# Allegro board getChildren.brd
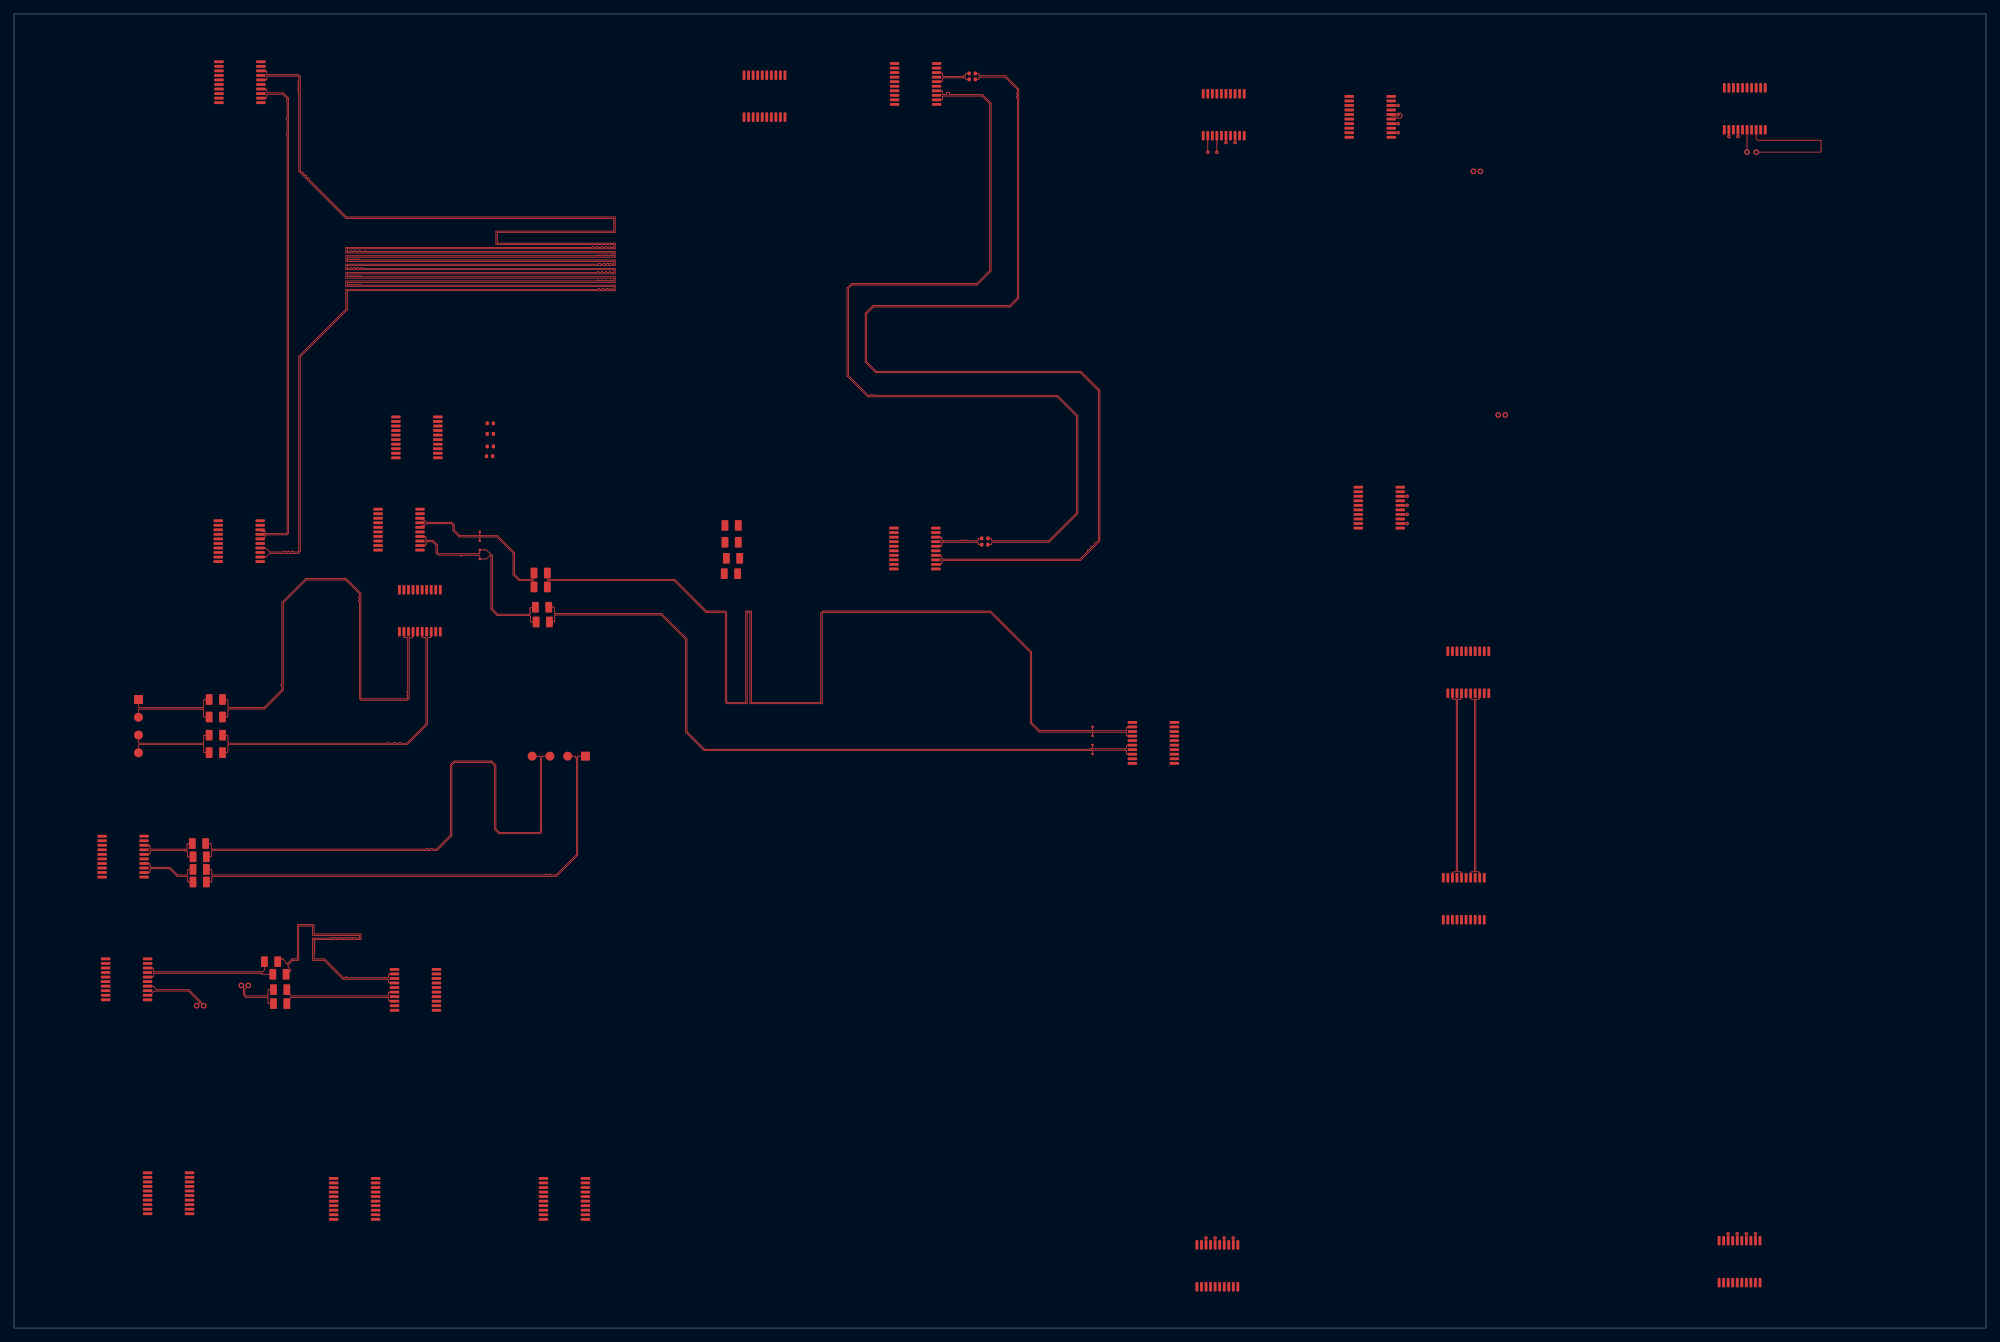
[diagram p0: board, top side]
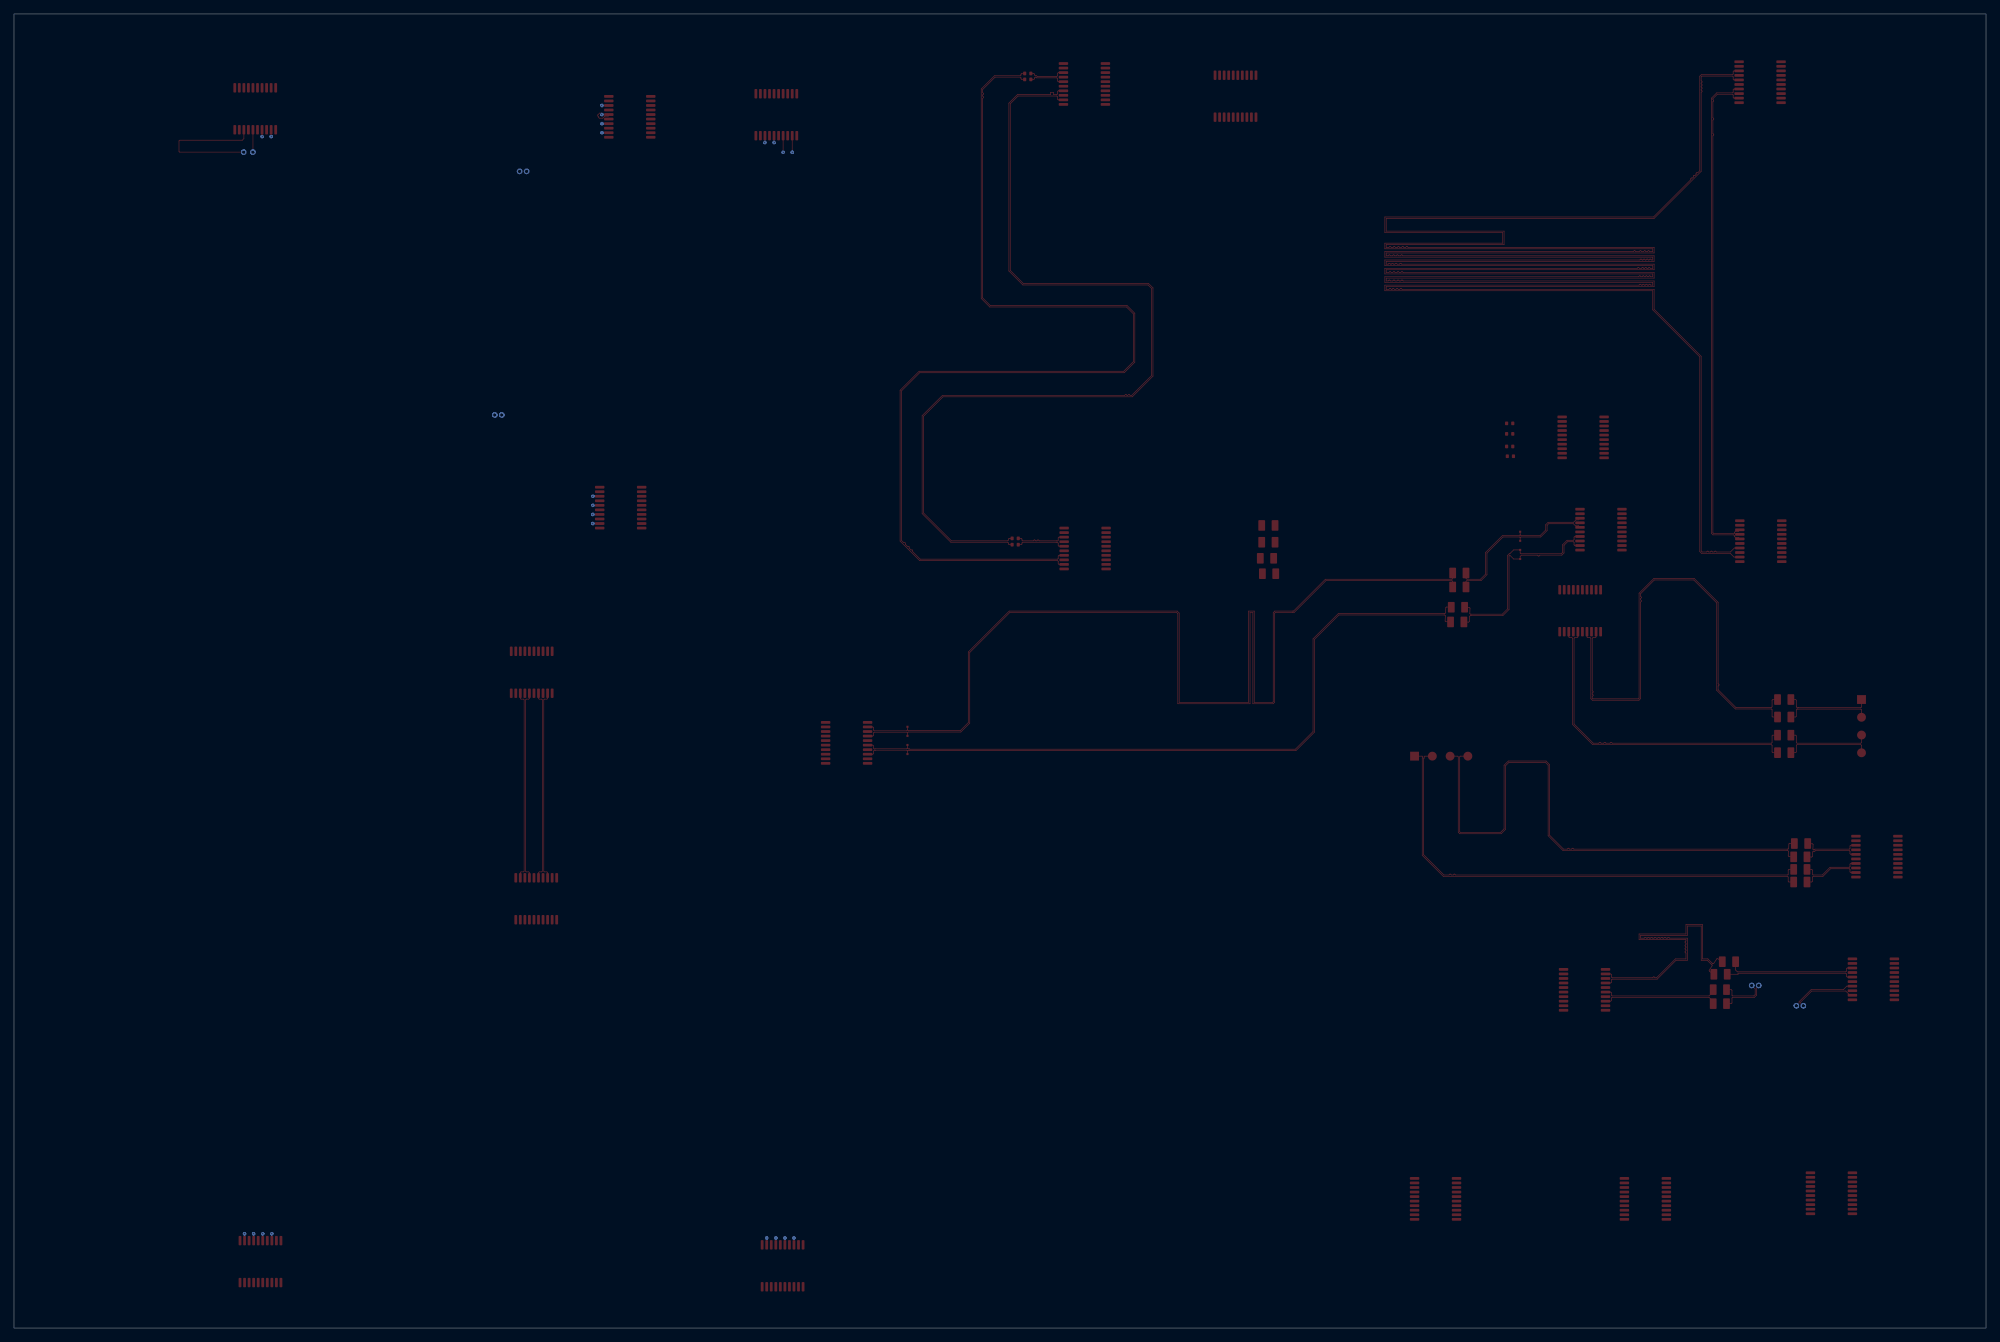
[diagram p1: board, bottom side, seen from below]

Outline 281.94 x 187.96 mm; copper layers: TOP, LAYER2, LAYER3, LAYER4, LAYER5, LAYER6, LAYER7, LAYER8, LAYER9, LAYER10, LAYER11, LAYER12, LAYER13, LAYER14, LAYER15, LAYER16, LAYER17, BOTTOM. Coordinates in mm from the lower left corner of the outline.
Outline path: 0,187.96 281.94,187.96 281.94,0 0,0 0,187.96

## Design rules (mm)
constraint set DEFAULT: min track width 0.1, pair gap 0.15
net group CLS1: nets NET_A_N NET_AAA_P
net group CONN_MIRROR_NET_G_N: nets CONN_MIRROR_NET_G_N UNNAMED_1_74244_I71_A_3
net group CONN_MIRROR_NET_G_P: nets CONN_MIRROR_NET_G_P UNNAMED_1_74244_I71_A_1
net group CONN_MIRROR_NET_H_N: nets CONN_MIRROR_NET_H_N UNNAMED_1_74244_I71_A_2
net group CONN_MIRROR_NET_H_P: nets CONN_MIRROR_NET_H_P UNNAMED_1_74244_I71_A
net group CONN_NET_G_N: nets CONN_NET_G_N UNNAMED_1_74244_I50_A_1
net group CONN_NET_G_P: nets CONN_NET_G_P UNNAMED_1_74244_I50_A
net group CONN_NET_H_N: nets CONN_NET_H_N UNNAMED_1_74244_I50_A_3
net group CONN_NET_H_P: nets CONN_NET_H_P UNNAMED_1_74244_I50_A_2
net group DP2: nets NET_AAA_N NET_BBB_N
net group NET_C_N: nets NET_C_N UNNAMED_1_74244_I6_A_2
net group NET_C_P: nets NET_C_P UNNAMED_1_74244_I6_A_3
net group NET_D_N: nets NET_D_N UNNAMED_1_74244_I6_A
net group NET_D_P: nets NET_D_P UNNAMED_1_74244_I6_A_1
net group NET_G_N: nets NET_G_N UNNAMED_1_74244_I12_A_2
net group NET_G_P: nets NET_G_P UNNAMED_1_74244_I12_A_3
net group NET_H_N: nets NET_H_N UNNAMED_1_74244_I12_A
net group NET_H_P: nets NET_H_P UNNAMED_1_74244_I12_A_1
net group TP_G_N: nets TP_G_N UNNAMED_1_74244_I44_A_2
net group TP_G_P: nets TP_G_P UNNAMED_1_74244_I44_A_3
net group TP_H_N: nets TP_H_N UNNAMED_1_74244_I44_A
net group TP_H_P: nets TP_H_P UNNAMED_1_74244_I44_A_1
net group DP1: nets NET_A_P
net group RC_NET_G_N: nets RC_NET_G_N UNNAMED_1_74244_I38_A_1 UNNAMED_1_74244_I39_Y
net group RC_NET_G_P: nets RC_NET_G_P UNNAMED_1_74244_I38_A UNNAMED_1_CAPUNPOL5_I34_A
net group RC_NET_H_N: nets RC_NET_H_N UNNAMED_1_74244_I38_A_3 UNNAMED_1_CAPUNPOL5_I36_A
net group RC_NET_H_P: nets RC_NET_H_P UNNAMED_1_74244_I38_A_2 UNNAMED_1_CAPUNPOL5_I35_A

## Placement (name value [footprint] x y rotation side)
C1  10p  [511-BYZ10902-70]  38.05 48.4 0 top
C2  10p  [511-BYZ10902-70]  36.75 52.4 0 top
C3  10p  [511-BYZ10902-70]  38.05 46.4 0 top
C4  10p  [511-BYZ10902-70]  37.95 50.6 0 top
C5  10p  [511-BYZ10902-70]  102.8 110.1 0 top
C6  10p  [511-BYZ10902-70]  75.5 103.1 0 top
C7  10p  [511-BYZ10902-70]  102.6 114.8 0 top
C8  10p  [511-BYZ10902-70]  75.3 108 0 top
C9  10p  [511-BYZ10902-70]  102.5 107.9 0 top
C10  10p  [511-BYZ10902-70]  75.6 101 0 top
C11  10p  [511-BYZ10902-70]  102.6 112.4 0 top
C12  10p  [511-BYZ10902-70]  75.3 106 0 top
C13  10p  [511-BYZ10902-70]  28.85 84.8 0 top
C14  10p  [511-BYZ10902-70]  28.85 89.9 0 top
C15  10p  [511-BYZ10902-70]  28.85 82.3 0 top
C16  10p  [511-BYZ10902-70]  28.85 87.4 0 top
C17  10p  [511-BYZ10902-70]  26.55 67.4 180 top
C18  10p  [511-BYZ10902-70]  26.55 63.8 180 top
C19  10p  [511-BYZ10902-70]  26.45 69.3 180 top
C20  10p  [511-BYZ10902-70]  26.55 65.6 180 top
D1  -  [511-BYZ20916-63_TOP]  32.3 178.2 270 top
D2  -  [511-BYZ20916-63_TOP]  128.9 177.95 270 top
D3  -  [511-BYZ20916-63_TOP]  22.1 19.27 270 top
D4  -  [511-BYZ20916-63_TOP]  16.1 49.88 270 top
D5  -  [511-BYZ20916-63_TOP]  32.2 112.55 90 top
D6  -  [511-BYZ20916-63_TOP]  128.8 111.5 90 top
D7  -  [511-BYZ20916-63_TOP]  57.4 48.38 270 top
D8  -  [511-BYZ20916-63_TOP]  78.7 18.48 270 top
D9  -  [511-BYZ20916-63_TOP]  48.7 18.48 270 top
D10  -  [511-BYZ20916-63_TOP]  193.9 173.25 270 top
D11  -  [511-BYZ20916-63_TOP]  247.45 174.4 0 top
D12  -  [511-BYZ20916-63_TOP]  195.2 117.35 90 top
D13  -  [511-BYZ20916-63_TOP]  246.7 9.5 0 top
D14  -  [511-BYZ20916-63_TOP]  172.95 173.55 0 top
D15  -  [511-BYZ20916-63_TOP]  172.05 8.9 0 top
D16  -  [511-BYZ20916-63_TOP]  57.6 127.4 270 top
D17  -  [511-BYZ20916-63_TOP]  55.05 114.2 270 top
D18  -  [511-BYZ20916-63_TOP]  107.3 176.2 0 top
D19  -  [511-BYZ20916-63_TOP]  162.9 83.7 270 top
D20  -  [511-BYZ20916-63_TOP]  58.02 102.6 0 top
D21  -  [511-BYZ20916-63_TOP]  207.28 61.4 0 top
D22  -  [511-BYZ20916-63_TOP]  207.93 93.8 0 top
D23  -  [511-BYZ20916-63_TOP]  15.6 67.42 90 top
R1  3.3k  [501-BYZ20902-48_TOP]  138.8 112.95 180 top
R2  3.3k  [501-BYZ20902-48_TOP]  137 179.45 0 top
R3  3.3k  [501-BYZ20902-48_TOP]  137 178.6 0 top
R4  3.3k  [501-BYZ20902-48_TOP]  138.8 112.05 180 top
R5  3.3k  [501-BYZ20902-48_TOP]  68.1 129.4 0 top
R6  3.3k  [501-BYZ20902-48_TOP]  68.1 127.9 0 top
R7  3.3k  [501-BYZ20902-48_TOP]  68.1 126.1 0 top
R8  3.3k  [501-BYZ20902-48_TOP]  68 124.7 0 top
TP1  -  [505-BYZ11988-1]  66.6 113.9 0 top
TP2  -  [505-BYZ11988-1]  66.6 112.6 0 top
TP3  -  [505-BYZ11988-1]  66.6 111.3 0 top
TP4  -  [505-BYZ11988-1]  66.6 110 0 top
TP5  -  [505-BYZ11988-1]  154.2 86 0 top
TP6  -  [505-BYZ11988-1]  154.2 82.1 0 top
TP7  -  [505-BYZ11988-1]  154.2 84.7 0 top
TP8  -  [505-BYZ11988-1]  154.2 83.4 0 top
X1  -  [501-BYZ10901-287]  17.8 89.9 0 top
X2  -  [501-BYZ10901-287]  81.7 81.8 270 top

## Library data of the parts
C1-C20 = RJC543458: alternate symbols: (T:511-BYZ10902-70,511-BYZ20902-70_TOP;B:511-BYZ10902-70,511-BYZ20902-70_BOT); part number: RJC543458-10P; signal model: DEFAULT_CAPACITOR_10.000000pF_2_1
D1-D23 = 74VHC244: alternate symbols: (T:511-BYZ20916-63_TOP;B:511-BYZ20916-63_BOT); part number: 74VHC244-RYT3356008/2C,74VHC244MTC
R1-R8 = REP62265: alternate symbols: (T:501-BYZ20902-48_TOP,501-BYZ10902-503;B:501-BYZ20902-48_BOT,501-BYZ10902-503); part number: REP62265-3.3K; signal model: DEFAULT_RESISTOR_3300OHM_2_1
TP1-TP8 = TP_RND_NH_48: alternate symbols: (505-BYZ11988-1); part number: TP_RND_NH_48-TP_RND_NH_48
X1 X2 = RPV403164/802: alternate symbols: (501-BYZ10901-287); part number: RPV403164/802-RPV403164/802

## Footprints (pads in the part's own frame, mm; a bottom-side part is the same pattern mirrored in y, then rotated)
501-BYZ10901-287
  rect 1.27x1.27 smd: 1(0,0)
  round 1.27 smd: 2(0,-2.54) J1(0,-5.08) J2(0,-7.62)
501-BYZ20902-48_TOP
  custom 0.114x0.114 smd: 1(-0.44,0) 2(0.44,0)
505-BYZ11988-1
  rect 0.3x0.3 smd: 1(0,0)
511-BYZ10902-70
  custom 0.242x0.242 smd: 1(-0.953,0) 2(0.953,0)
511-BYZ20916-63_TOP
  custom 0.1x0.1 smd: 1(-2.925,-3) 2(-2.275,-3) 3(-1.625,-3) 4(-0.975,-3) 5(-0.325,-3) 6(0.325,-3) 7(0.975,-3) 8(1.625,-3) 9(2.275,-3) 10(2.925,-3) 11(2.925,3) 12(2.275,3) 13(1.625,3) 14(0.975,3) 15(0.325,3) 16(-0.325,3) 17(-0.975,3) 18(-1.625,3) 19(-2.275,3) 20(-2.925,3)

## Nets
PGND: D3.10 D4.10 D5.10 D6.10 D7.10 D8.10 D9.10
CONN_MIRROR_NET_G_N: C20.1 X2.2(P<1>)
CONN_MIRROR_NET_G_P: C18.1 X2.1
CONN_MIRROR_NET_H_N: C19.1 X2.J2
CONN_MIRROR_NET_H_P: C17.1 X2.J1
CONN_NET_G_N: C16.1 X1.2(P<1>)
CONN_NET_G_P: C14.1 X1.1
CONN_NET_H_N: C15.1 X1.J2
CONN_NET_H_P: C13.1 X1.J1
NET_A_N: D1.16 D5.4
NET_A_P: D1.18 D5.2
NET_AAA_N: D10.16 D12.4
NET_AAA_P: D10.18 D12.2
NET_B_N: D1.12 D5.8
NET_B_P: D1.14 D5.6
NET_BBB_N: D10.12 D12.8
NET_BBB_P: D10.14 D12.6
NET_C_N: D2.16 R3.1
NET_C_P: D2.18 R2.1
NET_CCC_N: D11.4 D13.16
NET_CCC_P: D11.2 D13.18
NET_D_N: D2.12 R1.1
NET_D_P: D2.14 R4.1
NET_DDD_N: D11.8 D13.12
NET_DDD_P: D11.6 D13.14
NET_E_N: D3.16 D8.4 D9.4
NET_E_P: D3.18 D8.2 D9.2
NET_EEE_N: D14.4 D15.16
NET_EEE_P: D14.2 D15.18
NET_F_N: D3.12 D8.8 D9.8
NET_F_P: D3.14 D8.6 D9.6
NET_FFF_N: D14.8 D15.12
NET_FFF_P: D14.6 D15.14
NET_G_N: C4.1 D4.16
NET_G_P: C2.1 D4.18
NET_H_N: C3.1 D4.12
NET_H_P: C1.1 D4.14
P2_3V: D3.20(U+) D4.20(U+) D5.20(U+) D6.20(U+) D7.20(U+) D8.20(U+) D9.20(U+)
RC_NET_G_N: C11.1 R6.2(Y)
RC_NET_G_P: D16.18 R5.1
RC_NET_H_N: D16.12 R8.1
RC_NET_H_P: D16.14 R7.1
TP_G_N: C12.1 D17.16 TP2.1(P)
TP_G_P: C8.1 D17.18 TP1.1(P)
TP_H_N: C10.1 D17.12 TP4.1(P)
TP_H_P: C6.1 D17.14 TP3.1(P)
UNCOUPLED_NET_EEE_N: D21.16 D22.4
UNCOUPLED_NET_EEE_P: D21.18 D22.2
UNCOUPLED_NET_FFF_N: D21.12 D22.8
UNCOUPLED_NET_FFF_P: D21.14 D22.6
UNNAMED_1_74244_I6_A: D6.8 R1.2(Y)
UNNAMED_1_74244_I6_A_1: D6.6 R4.2(Y)
UNNAMED_1_74244_I6_A_2: D6.4 R3.2(Y)
UNNAMED_1_74244_I6_A_3: D6.2 R2.2(Y)
UNNAMED_1_74244_I12_A: C3.2(Y) D7.8
UNNAMED_1_74244_I12_A_1: C1.2(Y) D7.6
UNNAMED_1_74244_I12_A_2: C4.2(Y) D7.4
UNNAMED_1_74244_I12_A_3: C2.2(Y) D7.2
UNNAMED_1_74244_I38_A: C7.2(Y) D18.2
UNNAMED_1_74244_I38_A_1: C11.2(Y) D18.4
UNNAMED_1_74244_I38_A_2: C5.2(Y) D18.6
UNNAMED_1_74244_I38_A_3: C9.2(Y) D18.8
UNNAMED_1_74244_I39_Y: D16.16 R6.1
UNNAMED_1_74244_I44_A: C10.2(Y) D19.8 TP6.1(P)
UNNAMED_1_74244_I44_A_1: C6.2(Y) D19.6 TP8.1(P)
UNNAMED_1_74244_I44_A_2: C12.2(Y) D19.4 TP7.1(P)
UNNAMED_1_74244_I44_A_3: C8.2(Y) D19.2 TP5.1(P)
UNNAMED_1_74244_I50_A: C14.2(Y) D20.2
UNNAMED_1_74244_I50_A_1: C16.2(Y) D20.4
UNNAMED_1_74244_I50_A_2: C13.2(Y) D20.6
UNNAMED_1_74244_I50_A_3: C15.2(Y) D20.8
UNNAMED_1_74244_I71_A: C17.2(Y) D23.6
UNNAMED_1_74244_I71_A_1: C18.2(Y) D23.2
UNNAMED_1_74244_I71_A_2: C19.2(Y) D23.8
UNNAMED_1_74244_I71_A_3: C20.2(Y) D23.4
UNNAMED_1_CAPUNPOL5_I34_A: C7.1 R5.2(Y)
UNNAMED_1_CAPUNPOL5_I35_A: C5.1 R7.2(Y)
UNNAMED_1_CAPUNPOL5_I36_A: C9.1 R8.2(Y)

Pads without a net: D1 1 2 3 4 5 6 7 8 9 10 11 13 15 17 19 20; D2 1 2 3 4 5 6 7 8 9 10 11 13 15 17 19 20; D3 1 2 3 4 5 6 7 8 9 11 13 15 17 19; D4 1 2 3 4 5 6 7 8 9 11 13 15 17 19; D5 1 3 5 7 9 11 12 13 14 15 16 17 18 19; D6 1 3 5 7 9 11 12 13 14 15 16 17 18 19; D7 1 3 5 7 9 11 12 13 14 15 16 17 18 19; D8 1 3 5 7 9 11 12 13 14 15 16 17 18 19; D9 1 3 5 7 9 11 12 13 14 15 16 17 18 19; D10 1 2 3 4 5 6 7 8 9 10 11 13 15 17 19 20; D11 1 3 5 7 9 10 11 12 13 14 15 16 17 18 19 20; D12 1 3 5 7 9 10 11 12 13 14 15 16 17 18 19 20; D13 1 2 3 4 5 6 7 8 9 10 11 13 15 17 19 20; D14 1 3 5 7 9 10 11 12 13 14 15 16 17 18 19 20; D15 1 2 3 4 5 6 7 8 9 10 11 13 15 17 19 20; D16 1 2 3 4 5 6 7 8 9 10 11 13 15 17 19 20; D17 1 2 3 4 5 6 7 8 9 10 11 13 15 17 19 20; D18 1 3 5 7 9 10 11 12 13 14 15 16 17 18 19 20; D19 1 3 5 7 9 10 11 12 13 14 15 16 17 18 19 20; D20 1 3 5 7 9 10 11 12 13 14 15 16 17 18 19 20; D21 1 2 3 4 5 6 7 8 9 10 11 13 15 17 19 20; D22 1 3 5 7 9 10 11 12 13 14 15 16 17 18 19 20; D23 1 3 5 7 9 10 11 12 13 14 15 16 17 18 19 20

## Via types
v1: diameter 0.5, hole 0.2, TOP to BOTTOM, 22 vias
v2: diameter 0.8, hole 0.5, TOP to BOTTOM, 10 vias

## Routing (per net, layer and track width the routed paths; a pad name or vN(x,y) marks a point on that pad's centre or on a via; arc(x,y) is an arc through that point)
CONN_MIRROR_NET_G_N: length 70.2
  TOP w0.1: C20.1 28.18,65.6 28.28,65.5 28.28,64.9 28.38,64.8 75.83,64.8 75.95,64.92 76.05,64.92 76.17,64.8 76.43,64.8 76.55,64.92 76.65,64.92 76.77,64.8 77.5,64.8 80.4,67.7 80.4,81.45 80.33,81.52 80.33,81.7 80.23,81.8 X2.2
CONN_MIRROR_NET_G_P: length 70.4
  TOP w0.1: C18.1 28.18,63.8 28.28,63.9 28.28,64.5 28.38,64.6 77.58,64.6 80.6,67.62 80.6,81.53 80.53,81.6 80.53,81.7 80.63,81.8 X2.1
CONN_MIRROR_NET_H_N: length 81.4
  TOP w0.1: C19.1 28.08,69.34 28.19,69.24 28.22,68.59 28.33,68.5 28.42,68.5 58.93,68.5 59.05,68.62 59.15,68.62 59.27,68.5 59.53,68.5 59.65,68.62 59.75,68.62 59.87,68.5 60.4,68.5 62.4,70.5 62.4,80.6 62.9,81.1 68.3,81.1 68.9,80.5 68.9,71.4 69.4,70.9 75.15,70.9 75.25,71 75.25,81.7 75.15,81.8 X2.J2
CONN_MIRROR_NET_H_P: length 81.5
  TOP w0.1: C17.1 28.18,67.44 28.28,67.54 28.24,68.19 28.34,68.3 28.43,68.3 60.48,68.3 62.6,70.42 62.6,80.52 62.98,80.9 68.22,80.9 68.7,80.42 68.7,71.32 69.32,70.7 75.23,70.7 75.45,70.92 75.45,81.7 75.55,81.8 X2.J1
CONN_NET_G_N: length 12.3
  TOP w0.1: C16.1 27.22,87.4 27.12,87.5 27.12,88.45 27.02,88.55 26.92,88.55 26.9,88.53 17.9,88.53 17.8,88.43 X1.2
CONN_NET_G_P: length 12.3
  TOP w0.1: X1.1 17.8,88.83 17.9,88.73 26.82,88.73 26.84,88.75 27.02,88.75 27.12,88.85 27.12,89.8 27.22,89.9 C14.1
CONN_NET_H_N: length 12.2
  TOP w0.1: C15.1 27.22,82.3 27.12,82.4 27.12,83.35 27.02,83.45 17.9,83.45 17.8,83.35 X1.J2
CONN_NET_H_P: length 12.2
  TOP w0.1: X1.J1 17.8,83.75 17.9,83.65 27.02,83.65 27.12,83.75 27.12,84.7 27.22,84.8 C13.1
NET_A_N: length 581.6
  TOP w0.1: D5.4 35.98,111.58 36.55,111 38.53,111 38.65,111.12 38.75,111.12 38.87,111 39.08,111 39.2,111.12 39.3,111.12 39.42,111 39.63,111 39.75,111.12 39.85,111.12 39.97,111 40.58,111 40.73,111.15 40.73,139 47.45,145.72 47.45,148.58 83.48,148.58 83.6,148.7 83.7,148.7 83.82,148.58 84.03,148.58 84.15,148.7 84.25,148.7 84.37,148.58 84.58,148.58 84.7,148.7 84.8,148.7 84.92,148.58 85.03,148.58 85.15,148.7 85.25,148.7 85.37,148.58 85.75,148.58 85.75,148.98 47.45,148.98 47.45,149.78 83.33,149.78 83.45,149.9 83.55,149.9 83.67,149.78 83.88,149.78 84,149.9 84.1,149.9 84.22,149.78 84.48,149.78 84.6,149.9 84.7,149.9 84.82,149.78 85.13,149.78 85.25,149.9 85.35,149.9 85.47,149.78 85.75,149.78 85.75,150.18 47.45,150.18 47.45,150.98 83.33,150.98 83.45,151.1 83.55,151.1 83.67,150.98 83.88,150.98 84,151.1 84.1,151.1 84.22,150.98 84.48,150.98 84.6,151.1 84.7,151.1 84.82,150.98 85.03,150.98 85.15,151.1 85.25,151.1 85.37,150.98 85.75,150.98 85.75,151.38 47.45,151.38 47.45,152.18 83.53,152.18 83.65,152.3 83.75,152.3 83.87,152.18 84.18,152.18 84.3,152.3 84.4,152.3 84.52,152.18 84.69,152.18 84.81,152.3 84.91,152.3 85.03,152.18 85.13,152.18 85.25,152.3 85.35,152.3 85.47,152.18 85.75,152.18 85.75,152.58 47.45,152.58 47.45,153.38 83.38,153.38 83.5,153.5 83.6,153.5 83.72,153.38 83.98,153.38 84.1,153.5 84.2,153.5 84.32,153.38 84.53,153.38 84.65,153.5 84.75,153.5 84.87,153.38 85.13,153.38 85.25,153.5 85.35,153.5 85.47,153.38 85.75,153.38 85.75,153.78 47.45,153.78 47.45,154.58 82.63,154.58 82.75,154.7 82.85,154.7 82.97,154.58 83.23,154.58 83.35,154.7 83.45,154.7 83.57,154.58 83.83,154.58 83.95,154.7 84.05,154.7 84.17,154.58 84.43,154.58 84.55,154.7 84.65,154.7 84.77,154.58 85.03,154.58 85.15,154.7 85.25,154.7 85.37,154.58 85.75,154.58 85.75,154.98 68.9,154.98 68.9,156.9 85.75,156.9 85.75,158.72 47.45,158.72 40.73,165.45 40.73,176.73 40.6,176.85 40.6,176.95 40.73,177.07 40.73,177.18 40.6,177.3 40.6,177.4 40.73,177.52 40.73,177.63 40.6,177.75 40.6,177.85 40.73,177.97 40.73,178.08 40.6,178.2 40.6,178.3 40.73,178.42 40.73,178.97 40.62,179.07 36.25,179.07 36.15,178.97 36.15,178.62 36.05,178.53 D1.16
NET_A_P: length 581.4
  TOP w0.1: 35.2,110.28 36.02,110.28 36.55,110.8 40.66,110.8 40.92,111.07 40.92,138.92 47.65,145.64 47.65,148.38 85.95,148.38 85.95,149.18 49.6,149.18 49.48,149.3 49.38,149.3 49.26,149.18 49.16,149.18 49.04,149.3 48.94,149.3 48.82,149.18 48.72,149.18 48.6,149.3 48.5,149.3 48.38,149.18 48.27,149.18 48.15,149.3 48.05,149.3 47.93,149.18 47.65,149.18 47.65,149.58 85.95,149.58 85.95,150.38 49.67,150.38 49.55,150.5 49.45,150.5 49.33,150.38 49.16,150.38 49.04,150.5 48.94,150.5 48.82,150.38 48.72,150.38 48.6,150.5 48.5,150.5 48.38,150.38 48.27,150.38 48.15,150.5 48.05,150.5 47.93,150.38 47.65,150.38 47.65,150.78 85.95,150.78 85.95,151.58 49.87,151.58 49.75,151.7 49.65,151.7 49.53,151.58 49.27,151.58 49.15,151.7 49.05,151.7 48.93,151.58 48.82,151.58 48.7,151.7 48.6,151.7 48.48,151.58 48.32,151.58 48.2,151.7 48.1,151.7 47.98,151.58 47.65,151.58 47.65,151.98 85.95,151.98 85.95,152.78 49.5,152.78 49.38,152.9 49.28,152.9 49.16,152.78 49.05,152.78 48.93,152.9 48.83,152.9 48.71,152.78 48.61,152.78 48.49,152.9 48.39,152.9 48.27,152.78 48.17,152.78 48.05,152.9 47.95,152.9 47.83,152.78 47.65,152.78 47.65,153.18 85.95,153.18 85.95,153.98 50.42,153.98 50.3,154.1 50.2,154.1 50.08,153.98 49.57,153.98 49.45,154.1 49.35,154.1 49.23,153.98 48.97,153.98 48.85,154.1 48.75,154.1 48.63,153.98 48.42,153.98 48.3,154.1 48.2,154.1 48.08,153.98 47.65,153.98 47.65,154.38 85.95,154.38 85.95,155.18 69.1,155.18 69.1,156.7 85.95,156.7 85.95,158.93 47.53,158.93 42.2,164.26 42.2,164.43 42.13,164.5 41.96,164.5 41.82,164.63 41.82,164.8 41.75,164.87 41.58,164.87 41.45,165.01 41.45,165.18 41.38,165.25 41.21,165.25 40.92,165.53 40.92,179.06 40.71,179.28 36.25,179.28 36.15,179.38 36.15,179.72 36.05,179.82 D1.18
NET_AAA_N: length 107
  TOP w0.1: D12.4 v1(199.18,116.38) ; D10.16 196.9,173.45 197,173.35 197.46,173.35 197.76,173.05 198.25,173.05 198.35,173.15 198.35,173.25 198.48,173.38 198.48,173.52 198.22,173.78 198.08,173.78 v1(197.88,173.57)
  LAYER5 w0.1: v2(212.2,130.6) 212.6,130.2 212.6,118.48 209.94,115.83 199.28,115.83 199.18,115.92 v1(199.18,116.38) ; v1(197.88,173.57) 197.88,174.03 197.97,174.12 205.09,174.12 209.05,170.17 209.05,165.85 v2(208.65,165.45)
  LAYER6 w0.1: v2(212.2,130.6) 212.6,131 212.6,146.54 212.48,146.66 212.48,146.76 212.6,146.88 212.6,146.98 212.48,147.1 212.48,147.2 212.6,147.32 212.6,147.52 211.47,148.65 207.37,148.65 204.85,151.17 204.85,153.23 205.77,154.15 215.47,154.15 216.25,154.93 216.25,162.07 215.52,162.8 214.37,162.8 214.25,162.68 214.15,162.68 214.03,162.8 213.77,162.8 213.65,162.68 213.55,162.68 213.43,162.8 210.47,162.8 209.05,164.22 209.05,165.05 v2(208.65,165.45)
NET_AAA_P: length 106.5
  TOP w0.1: D10.18 v1(197.88,174.88) ; 198.2,115.08 v1(199.18,115.08)
  LAYER5 w0.1: v2(213.2,130.6) 212.8,130.2 212.8,118.4 210.5,116.1 210.5,115.92 210.43,115.85 210.25,115.85 210.03,115.62 209.57,115.62 209.45,115.5 209.35,115.5 209.23,115.62 209.02,115.62 208.9,115.5 208.8,115.5 208.68,115.62 208.47,115.62 208.35,115.5 208.25,115.5 208.13,115.62 207.82,115.62 207.7,115.5 207.6,115.5 207.48,115.62 206.97,115.62 206.85,115.5 206.75,115.5 206.63,115.62 206.22,115.62 206.1,115.5 206,115.5 205.88,115.62 205.47,115.62 205.35,115.5 205.25,115.5 205.13,115.62 204.72,115.62 204.6,115.5 204.5,115.5 204.38,115.62 203.87,115.62 203.75,115.5 203.65,115.5 203.53,115.62 203.37,115.62 203.25,115.5 203.15,115.5 203.03,115.62 199.28,115.62 199.18,115.53 v1(199.18,115.08) ; v2(209.65,165.45) 209.25,165.85 209.25,170.25 205.17,174.32 204.07,174.32 203.95,174.45 203.85,174.45 203.73,174.32 197.97,174.32 197.88,174.43 v1(197.88,174.88)
  LAYER6 w0.1: v2(213.2,130.6) 212.8,131 212.8,147.6 211.55,148.85 207.45,148.85 205.05,151.25 205.05,153.15 205.85,153.95 215.55,153.95 216.45,154.85 216.45,162.15 215.6,163 212.67,163 212.55,163.12 212.45,163.12 212.33,163 210.55,163 209.25,164.3 209.25,165.05 v2(209.65,165.45)
NET_B_N: length 71
  TOP w0.1: D1.12 36.05,175.93 36.15,176.03 36.15,176.38 36.25,176.47 38.42,176.47 39.05,175.84 39.05,175.72 38.96,175.63 38.96,175.49 39.05,175.4 39.05,173.12 38.93,173 38.93,172.9 39.05,172.78 39.05,170.87 38.93,170.75 38.93,170.65 39.05,170.53 39.05,113.75 38.95,113.65 35.98,113.65 35.98,113.82 35.84,113.95 35.42,113.95 D5.8
NET_B_P: length 71.4
  TOP w0.1: D1.14 36.05,177.22 36.15,177.12 36.15,176.78 36.25,176.68 38.5,176.68 39.25,175.93 39.25,113.67 39.03,113.45 36.08,113.45 35.98,113.34 35.98,113.23 35.84,113.1 35.42,113.1 D5.6
NET_BBB_N: length 2
  TOP w0.1: D10.12 v1(197.88,170.97) ; D12.8 v1(199.18,118.97)
NET_BBB_P: length 2
  TOP w0.1: D10.14 v1(197.88,172.28) ; D12.6 v1(199.18,117.67)
NET_C_N: length 5.3
  TOP w0.1: R3.1 136.13,178.6 136.03,178.7 136.03,178.82 135.93,178.93 135.83,178.93 135.73,178.82 132.85,178.82 132.75,178.72 132.75,178.38 132.65,178.28 131.9,178.28
NET_C_P: length 5.3
  TOP w0.1: D2.18 132.65,179.57 132.75,179.47 132.75,179.12 132.85,179.03 135.65,179.03 135.75,179.12 135.93,179.12 136.03,179.22 136.03,179.35 136.13,179.45 R2.1
NET_CCC_N: length 173.9
  TOP w0.1: D11.4 v1(246.47,170.43) ; D13.16 v1(246.38,13.47)
  LAYER6 w0.1: v1(246.38,13.47) 245.93,13.47 245.82,13.57 245.82,112.74 246.12,113.04 246.12,114.06 245.93,114.26 245.93,157.92 246.5,157.92 246.5,158.32 245.93,158.32 245.93,158.72 246.5,158.72 246.5,159.12 245.93,159.12 245.93,159.52 246.5,159.52 246.5,159.92 245.93,159.92 245.93,160.32 246.5,160.32 246.5,160.72 245.93,160.72 245.93,161.12 246.5,161.12 246.5,161.52 245.93,161.52 245.93,161.92 246.5,161.92 246.5,162.32 245.93,162.32 245.93,162.72 246.5,162.72 246.5,163.12 245.93,163.12 245.93,163.52 246.5,163.52 246.5,163.92 245.93,163.92 245.93,164.32 246.5,164.32 246.5,164.72 245.93,164.72 245.93,165.12 246.5,165.12 246.5,165.52 245.93,165.52 245.93,165.92 246.5,165.92 246.5,166.32 245.93,166.32 245.93,166.72 246.5,166.72 246.5,167.12 245.93,167.12 245.93,170.32 246.03,170.43 v1(246.47,170.43)
NET_CCC_P: length 174
  TOP w0.1: 245.18,171.4 v1(245.18,170.43) ; D13.18 v1(245.07,13.47)
  LAYER6 w0.1: v1(245.18,170.43) 245.62,170.43 245.72,170.32 245.72,169.73 238.75,169.73 238.75,168.25 245.72,168.25 245.72,114.17 245.93,113.97 245.93,113.12 245.62,112.83 245.62,13.57 245.53,13.47 v1(245.07,13.47)
NET_D_N: length 129.9
  TOP w0.1: R1.1 139.67,112.95 139.77,112.85 139.77,112.7 139.87,112.6 147.92,112.6 151.9,116.58 151.9,130.42 149.12,133.2 122.06,133.2 119.1,136.16 119.1,148.78 119.72,149.4 137.62,149.4 139.5,151.28 139.5,175.12 138.39,176.22 132.85,176.22 132.75,176.12 132.75,175.78 132.65,175.68 131.9,175.68
NET_D_P: length 131.5
  TOP w0.1: R4.1 139.67,112.05 139.77,112.15 139.77,112.3 139.87,112.4 148,112.4 152.1,116.5 152.1,130.5 149.2,133.4 123.15,133.4 123.03,133.52 122.93,133.52 122.81,133.4 122.71,133.4 122.59,133.52 122.49,133.52 122.37,133.4 122.14,133.4 119.3,136.24 119.3,148.7 119.8,149.2 137.7,149.2 139.7,151.2 139.7,175.2 138.47,176.43 133.73,176.43 133.73,176.75 133.33,176.75 133.33,176.43 132.85,176.43 132.75,176.53 132.75,176.88 132.65,176.97 D2.14
NET_DDD_N: length 178.1
  TOP w0.1: v2(249.1,168.2) 258.25,168.2 258.35,168.3 258.35,169.8 258.25,169.9 249.3,169.9 249.07,170.12 D11.8 ; D13.12 v1(248.97,13.47)
  LAYER6 w0.1: v2(249.1,168.2) 248.54,167.64 248.54,114.25 248.72,114.06 248.72,13.97 248.43,13.68 248.43,13.57 248.53,13.47 v1(248.97,13.47)
NET_DDD_P: length 175.3
  TOP w0.1: 247.78,171.4 v2(247.78,168.2) ; 247.68,12.5 v1(247.68,13.47)
  LAYER6 w0.1: v1(247.68,13.47) 248.12,13.47 248.22,13.57 248.22,13.76 248.53,14.06 248.53,113.97 248.34,114.16 248.34,161.27 247.05,161.27 247.05,161.67 248.34,161.67 248.34,162.07 247.05,162.07 247.05,162.47 248.34,162.47 248.34,162.87 247.05,162.87 247.05,163.27 248.34,163.27 248.34,163.67 247.05,163.67 247.05,164.07 248.34,164.07 248.34,164.47 247.05,164.47 247.05,164.87 248.34,164.87 248.34,165.27 247.05,165.27 247.05,165.67 248.34,165.67 248.34,167.64 v2(247.78,168.2)
NET_EEE_N: length 322.1
  TOP w0.1: 171.72,11.9 v1(171.72,12.88) ; v1(171.97,168.18) D14.4
  LAYER6 w0.1: v1(171.97,168.18) 171.53,168.18 171.43,168.07 171.43,157.2 171.43,157.2 171.43,157.03 170.72,156.33 153.91,156.33 153.25,155.67 153.25,152.53 153.32,152.46 153.49,152.46 153.56,152.39 153.56,152.22 153.63,152.15 153.8,152.15 153.88,152.08 153.88,151.91 154.73,151.05 154.83,151.05 154.95,151.17 155.05,151.17 155.17,151.05 155.33,151.05 155.45,151.17 155.55,151.17 155.67,151.05 170.33,151.05 170.55,150.83 170.55,146.92 170.33,146.7 150.53,146.7 147.55,143.72 147.55,143.58 147.65,143.49 147.82,143.49 147.89,143.42 147.89,143.25 147.96,143.17 148.13,143.17 148.2,143.1 148.2,142.93 148.27,142.86 148.44,142.86 148.51,142.79 148.51,142.62 161.4,129.73 161.55,129.73 161.77,129.95 161.98,129.95 162.1,130.07 162.2,130.07 162.32,129.95 162.43,129.95 162.55,130.07 162.65,130.07 162.77,129.95 168.48,129.95 170.9,127.53 170.9,50.17 167.03,46.3 125.43,46.3 122.15,43.02 122.15,42.42 122.27,42.3 122.27,42.2 122.15,42.08 122.15,40.58 122.3,40.44 122.47,40.44 122.54,40.37 122.54,40.2 122.67,40.06 122.84,40.06 122.91,39.99 122.91,39.82 124.98,37.75 125.33,37.75 125.45,37.87 125.55,37.87 125.67,37.75 125.77,37.75 125.89,37.87 125.99,37.87 126.11,37.75 170.53,37.75 171.2,37.08 171.2,13.84 171.49,13.84 171.49,13.44 171.2,13.44 171.2,13.1 171.18,13.07 171.18,12.97 171.28,12.88 v1(171.72,12.88)
NET_EEE_P: length 322.4
  TOP w0.1: D15.18 v1(170.43,12.88) ; 170.68,170.55 v1(170.68,168.18)
  LAYER6 w0.1: v1(170.43,12.88) 170.88,12.88 170.97,12.97 170.97,13.16 171,13.18 171,36.23 170.88,36.35 170.88,36.45 171,36.57 171,37 170.45,37.55 124.9,37.55 121.95,40.5 121.95,43.1 125.35,46.5 166.03,46.5 166.15,46.62 166.25,46.62 166.37,46.5 166.48,46.5 166.6,46.62 166.7,46.62 166.82,46.5 166.95,46.5 170.04,49.59 170.04,49.76 170.11,49.83 170.28,49.83 170.35,49.9 170.35,50.08 170.42,50.15 170.6,50.15 170.7,50.25 170.7,126.93 170.58,127.05 170.58,127.15 170.7,127.27 170.7,127.45 168.4,129.75 161.85,129.75 161.63,129.53 161.32,129.53 147.35,143.5 147.35,143.8 150.45,146.9 168.38,146.9 168.5,147.02 168.6,147.02 168.72,146.9 168.83,146.9 168.95,147.02 169.05,147.02 169.17,146.9 169.28,146.9 169.4,147.02 169.5,147.02 169.62,146.9 169.73,146.9 169.85,147.02 169.95,147.02 170.07,146.9 170.25,146.9 170.35,147 170.35,150.23 170.23,150.35 170.23,150.45 170.35,150.57 170.35,150.75 170.25,150.85 154.65,150.85 153.05,152.45 153.05,155.75 153.83,156.53 170.64,156.53 171.22,157.12 171.22,161.98 171.1,162.1 171.1,162.2 171.22,162.32 171.22,162.45 171.1,162.57 171.1,162.67 171.22,162.79 171.22,162.97 171.1,163.09 171.1,163.19 171.22,163.31 171.22,163.48 171.1,163.6 171.1,163.7 171.22,163.82 171.22,164.02 171.1,164.14 171.1,164.24 171.22,164.36 171.22,164.51 171.1,164.63 171.1,164.73 171.22,164.85 171.22,164.99 171.1,165.11 171.1,165.21 171.22,165.33 171.22,165.43 171.1,165.55 171.1,165.65 171.22,165.77 171.22,165.88 171.1,166 171.1,166.1 171.22,166.22 171.22,166.42 171.1,166.54 171.1,166.64 171.22,166.76 171.22,166.87 171.1,166.99 171.1,167.09 171.22,167.21 171.22,167.36 171.1,167.48 171.1,167.58 171.22,167.7 171.22,168.07 171.12,168.18 v1(170.68,168.18)
NET_FFF_N: length 196.3
  TOP w0.1: v1(174.57,169.57) D14.8 ; 174.32,11.9 v1(174.32,12.88)
  LAYER6 w0.1: v1(174.57,169.57) 174.12,169.57 174.03,169.47 174.03,101.98 179.65,96.36 179.65,91.64 174.03,86.02 174.03,84.73 174.12,84.63 189.74,84.63 190.65,83.72 190.65,82.44 190.65,82.44 190.65,82.28 189.44,81.07 174.12,81.07 174.03,80.97 174.03,14.39 173.78,14.14 173.78,12.97 173.88,12.88 v1(174.32,12.88)
NET_FFF_P: length 196.3
  TOP w0.1: 173.28,170.55 v1(173.28,169.57) ; D15.14 v1(173.03,12.88)
  LAYER6 w0.1: v1(173.03,12.88) 173.47,12.88 173.57,12.97 173.57,14.22 173.82,14.47 173.82,81.05 174.04,81.27 189.36,81.27 190.45,82.36 190.45,83.64 189.66,84.43 174.04,84.43 173.82,84.65 173.82,86.1 179.45,91.72 179.45,96.28 173.82,101.9 173.82,169.47 173.72,169.57 v1(173.28,169.57)
NET_G_N: length 18.5
  TOP w0.1: D4.16 19.85,50.2 19.95,50.3 19.95,50.65 20.05,50.75 35.45,50.75 35.45,50.6 C4.1
NET_G_P: length 18.4
  TOP w0.1: C2.1 35.8,51.2 35.55,50.95 20.05,50.95 19.95,51.05 19.95,51.4 19.85,51.5 D4.18
NET_H_N: length 35.3
  TOP w0.1: D4.12 19.45,47.6 20.05,48.2 24.92,48.2 26.52,46.6 26.52,46.5 v2(26.12,46.1) ; v2(32.5,49) 32.8,48.7 32.8,47.62 33.12,47.3 36.22,47.3 36.32,47.2 36.32,46.5 36.42,46.4 C3.1
  LAYER5 w0.1: v2(32.5,49) 32.9,49.4 32.9,50.92 32.72,51.1 31.38,51.1 29.9,49.62 29.9,44.32 27.58,42 26.72,42 26.2,42.52 26.2,44.8 26.12,44.88 v2(26.12,46.1)
NET_H_P: length 35.6
  TOP w0.1: C1.1 36.42,48.4 36.32,48.3 36.32,47.6 36.22,47.5 33.2,47.5 33,47.7 33,48.5 v2(33.5,49) ; v2(27.12,46.1) 26.72,46.5 26.72,46.68 25,48.4 20.4,48.4 19.9,48.9 D4.14
  LAYER5 w0.1: v2(27.12,46.1) 26.4,45.38 26.4,42.6 26.8,42.2 27.5,42.2 29.7,44.4 29.7,49.7 31.3,51.3 32.8,51.3 33.1,51 33.1,49.4 v2(33.5,49)
TP_G_N: length 23.5
  TOP w0.1: C12.1 74.35,106.8 74.25,106.9 72.2,106.9 71.35,107.75 71.35,110.85 69.05,113.15 66.7,113.15 66.6,113.05 ; 66.6,113.05 TP2.1 ; 66.6,113.05 66.5,113.15 63.67,113.15 62.75,114.07 62.75,114.82 62.52,115.05 59,115.05 58.7,114.75 58.27,114.75 D17.16
TP_G_P: length 23.5
  TOP w0.1: 66.6,113.45 66.5,113.35 63.75,113.35 62.95,114.15 62.95,114.9 62.6,115.25 58.98,115.25 58.62,115.6 58.27,115.6 D17.18 ; 66.6,113.45 TP1.1 ; 66.6,113.45 66.7,113.35 69.13,113.35 71.55,110.93 71.55,107.83 72.28,107.1 74.2,107.1 74.35,107.25 C8.1
TP_H_N: length 28.1
  TOP w0.1: 74.65,101 73.97,100.97 73.86,101.06 73.83,101.81 73.72,101.91 73.62,101.9 69.07,101.9 68.19,102.78 68.19,110.44 68.08,110.55 67.53,110 TP4.1 66.6,110.38 66.42,110.55 64.14,110.55 64.02,110.43 63.91,110.43 63.79,110.56 60.65,110.56 60.34,110.87 60.34,111.96 59.82,112.47 59,112.47 58.9,112.38 58.9,112.03 58.8,111.92 D17.12
TP_H_P: length 28
  TOP w0.1: 58.05,113.22 58.8,113.22 58.9,113.12 58.9,112.78 59,112.67 59.9,112.67 60.53,112.04 60.53,110.95 60.73,110.75 66.5,110.75 66.6,110.86 TP3.1 67.53,111.3 68.08,110.75 68.17,110.75 68.39,110.52 68.39,102.86 69.16,102.1 73.61,102.1 73.71,102.11 73.81,102.21 73.77,102.96 73.87,103.07 C6.1
UNCOUPLED_NET_EEE_N: length 27.3
  TOP w0.1: D21.16 206.95,65.15 206.85,65.25 206.5,65.25 206.4,65.35 206.4,89.85 206.5,89.95 206.85,89.95 206.95,90.05 D22.4
UNCOUPLED_NET_EEE_P: length 27.3
  TOP w0.1: D21.18 205.65,65.15 205.75,65.25 206.1,65.25 206.2,65.35 206.2,89.85 206.1,89.95 205.75,89.95 205.65,90.05 D22.2
UNCOUPLED_NET_FFF_N: length 27.3
  TOP w0.1: D21.12 209.55,65.15 209.45,65.25 209.1,65.25 209,65.35 209,89.85 209.1,89.95 209.45,89.95 209.55,90.05 D22.8
UNCOUPLED_NET_FFF_P: length 27.3
  TOP w0.1: D22.6 208.25,90.05 208.35,89.95 208.7,89.95 208.8,89.85 208.8,65.35 208.7,65.25 208.35,65.25 208.25,65.15 D21.14
UNNAMED_1_74244_I6_A: length 7.4
  TOP w0.1: R1.2 137.93,112.95 137.83,112.85 137.83,112.7 137.73,112.6 136.21,112.6 136.09,112.72 135.99,112.72 135.87,112.6 135.7,112.6 135.58,112.72 135.48,112.72 135.36,112.6 132.87,112.6 132.85,112.58 132.75,112.58 132.65,112.67 132.65,113.03 132.55,113.12 D6.8
UNNAMED_1_74244_I6_A_1: length 7.2
  TOP w0.1: D6.6 132.55,111.83 132.65,111.92 132.65,112.28 132.75,112.38 132.93,112.38 132.95,112.4 137.73,112.4 137.83,112.3 137.83,112.15 137.93,112.05 R4.2
UNNAMED_1_74244_I6_A_2: length 148.2
  TOP w0.1: R3.2 137.87,178.6 137.97,178.7 137.97,178.82 138.07,178.93 141.68,178.93 143.45,177.15 143.45,176.72 143.33,176.6 143.33,176.5 143.45,176.38 143.45,176.22 143.33,176.1 143.33,176 143.45,175.88 143.45,147.35 142.35,146.25 122.8,146.25 121.7,145.15 121.7,138.15 123.2,136.65 152.45,136.65 155.05,134.05 155.05,112.65 154.75,112.35 154.57,112.35 154.5,112.28 154.5,112.1 154.2,111.8 154.02,111.8 153.95,111.73 153.95,111.55 153.7,111.3 153.52,111.3 153.45,111.23 153.45,111.05 152.38,109.97 132.75,109.97 132.65,110.08 132.65,110.42 132.55,110.53 D6.4
UNNAMED_1_74244_I6_A_3: length 148.3
  TOP w0.1: D6.2 132.55,109.22 132.65,109.33 132.65,109.67 132.75,109.78 152.46,109.78 155.25,112.57 155.25,134.13 152.53,136.85 123.28,136.85 121.9,138.23 121.9,145.07 122.88,146.05 142.43,146.05 143.65,147.27 143.65,177.23 141.76,179.12 138.07,179.12 137.97,179.22 137.97,179.35 137.87,179.45 R2.2
UNNAMED_1_74244_I12_A: length 16.4
  TOP w0.1: D7.8 53.65,46.75 53.55,46.85 53.55,47.2 53.45,47.3 39.6,47.3 39.01,46.71 C3.2
UNNAMED_1_74244_I12_A_1: length 16.4
  TOP w0.1: D7.6 53.65,48.05 53.55,47.95 53.55,47.6 53.45,47.5 39.6,47.5 39.01,48.09 C1.2
UNNAMED_1_74244_I12_A_2: length 42.9
  TOP w0.1: D7.4 53.65,49.35 53.55,49.45 53.55,49.8 53.45,49.9 47.02,49.9 44.32,52.6 42.7,52.6 42.7,55.76 45.23,55.76 45.35,55.89 45.45,55.89 45.57,55.76 45.73,55.76 45.85,55.89 45.95,55.89 46.07,55.76 46.19,55.76 46.31,55.89 46.41,55.89 46.53,55.76 46.63,55.76 46.75,55.89 46.85,55.89 46.97,55.76 47.13,55.76 47.25,55.89 47.35,55.89 47.47,55.76 47.65,55.76 47.77,55.89 47.87,55.89 47.99,55.76 48.09,55.76 48.21,55.89 48.31,55.89 48.43,55.76 48.53,55.76 48.65,55.89 48.75,55.89 48.87,55.76 49.4,55.76 49.4,56.16 42.7,56.16 42.7,57.5 40.71,57.5 40.71,52.6 39.85,52.6 39.28,52.03 39.18,51.96 39.15,51.82 39.58,51.17 39.55,51.03 C4.2
UNNAMED_1_74244_I12_A_3: length 42.7
  TOP w0.1: C2.2 38.35,52.83 38.49,52.8 38.93,52.15 39.07,52.13 39.15,52.18 39.77,52.8 40.51,52.8 40.51,57.7 42.9,57.7 42.9,56.36 49.6,56.36 49.6,55.56 42.9,55.56 42.9,55.37 43.02,55.25 43.02,55.15 42.9,55.03 42.9,54.87 43.02,54.75 43.02,54.65 42.9,54.53 42.9,54.43 43.02,54.31 43.02,54.21 42.9,54.09 42.9,53.97 43.02,53.85 43.02,53.75 42.9,53.63 42.9,52.8 44.4,52.8 47.1,50.1 47.33,50.1 47.45,50.22 47.55,50.22 47.67,50.1 53.45,50.1 53.55,50.2 53.55,50.55 53.65,50.65 D7.2
UNNAMED_1_74244_I44_A: length 101
  TOP w0.1: D19.8 159.15,82.08 159.05,82.17 159.05,82.53 158.95,82.62 158.77,82.62 158.75,82.65 154.3,82.65 154.2,82.55 ; 154.2,82.55 TP6.1 ; 154.2,82.55 154.1,82.65 154,82.65 153.94,82.59 98.66,82.59 96.02,85.23 96.02,98.49 92.51,102 77.48,102 77.39,101.99 77.29,101.89 77.33,101.14 77.23,101.03 C10.2
UNNAMED_1_74244_I44_A_1: length 101
  TOP w0.1: 154.2,82.95 154.3,82.85 158.83,82.85 158.85,82.83 158.95,82.83 159.05,82.92 159.05,83.28 159.15,83.38 D19.6 ; 154.2,82.95 154.1,82.85 153.92,82.85 153.86,82.79 98.74,82.79 96.22,85.31 96.22,98.58 92.59,102.2 77.48,102.2 77.38,102.19 77.27,102.29 77.24,103.04 77.13,103.13 C6.2 ; 154.2,82.95 TP8.1
UNNAMED_1_74244_I44_A_2: length 152.2
  TOP w0.1: 154.2,85.15 154.1,85.25 146.57,85.25 145.3,86.52 145.3,96.62 139.57,102.35 115.72,102.35 115.55,102.18 115.55,89.3 105.22,89.3 105.22,102.35 104.82,102.35 104.82,89.3 101.92,89.3 101.7,89.52 101.7,102.25 101.6,102.35 99.17,102.35 98.92,102.35 94.37,106.9 76.35,106.9 76.25,106.8 C12.2 ; 154.2,85.15 TP7.1 ; 154.2,85.15 154.28,85.22 158.95,85.22 159.05,85.12 159.05,84.78 159.15,84.67 D19.4
UNNAMED_1_74244_I44_A_3: length 152.2
  TOP w0.1: 154.2,85.55 TP5.1 ; 154.2,85.55 154.1,85.45 146.65,85.45 145.5,86.6 145.5,96.7 139.65,102.55 115.64,102.55 115.35,102.26 115.35,89.5 105.42,89.5 105.42,102.55 104.62,102.55 104.62,89.5 102,89.5 101.9,89.6 101.9,102.33 101.68,102.55 99,102.55 94.45,107.1 76.35,107.1 76.25,107.2 C8.2 ; 154.2,85.55 154.32,85.42 158.95,85.42 159.05,85.53 159.05,85.88 159.15,85.97 D19.2
UNNAMED_1_74244_I50_A: length 68.7
  TOP w0.1: C14.2 30.49,89.9 30.59,89.8 30.59,88.85 30.69,88.75 35.75,88.75 38.3,91.3 38.3,91.83 38.18,91.95 38.18,92.05 38.3,92.17 38.3,103.8 41.7,107.2 47.5,107.2 49.6,105.1 49.6,90.1 49.7,90 56.2,90 56.3,90.1 56.3,90.33 56.18,90.45 56.18,90.55 56.3,90.67 56.3,90.83 56.18,90.95 56.18,91.05 56.3,91.17 56.3,98.65 56.2,98.75 55.85,98.75 55.75,98.85 D20.2
UNNAMED_1_74244_I50_A_1: length 68.9
  TOP w0.1: C16.2 30.49,87.4 30.59,87.5 30.59,88.45 30.69,88.55 35.83,88.55 38.5,91.22 38.5,103.72 41.78,107 47.42,107 49.4,105.02 49.4,104.67 49.28,104.55 49.28,104.45 49.4,104.33 49.4,104.17 49.28,104.05 49.28,103.95 49.4,103.83 49.4,90.02 49.62,89.8 56.28,89.8 56.5,90.02 56.5,98.65 56.6,98.75 56.95,98.75 57.05,98.85 D20.4
UNNAMED_1_74244_I50_A_2: length 45.2
  TOP w0.1: C13.2 30.49,84.8 30.59,84.7 30.59,83.75 30.69,83.65 53.43,83.65 53.55,83.77 53.65,83.77 53.77,83.65 54.33,83.65 54.45,83.77 54.55,83.77 54.67,83.65 55.03,83.65 55.15,83.77 55.25,83.77 55.37,83.65 56.15,83.65 58.9,86.4 58.9,98.65 58.8,98.75 58.45,98.75 58.35,98.85 D20.6
UNNAMED_1_74244_I50_A_3: length 45.2
  TOP w0.1: C15.2 30.49,82.3 30.59,82.4 30.59,83.35 30.69,83.45 56.23,83.45 59.1,86.32 59.1,98.65 59.2,98.75 59.55,98.75 59.65,98.85 D20.8
UNNAMED_1_74244_I71_A: length 8.2
  TOP w0.1: D23.6 19.35,67.75 19.45,67.85 19.45,68.2 19.55,68.3 24.37,68.3 24.48,68.19 24.67,68.2 24.77,68.11 24.81,67.46 24.91,67.36 C17.2
UNNAMED_1_74244_I71_A_1: length 8.6
  TOP w0.1: C18.2 24.91,63.8 24.81,63.9 24.81,64.5 24.71,64.6 23.32,64.6 22.22,65.7 19.55,65.7 19.45,65.6 19.45,65.25 19.35,65.15 D23.2
UNNAMED_1_74244_I71_A_2: length 8.1
  TOP w0.1: D23.8 19.35,69.05 19.45,68.95 19.45,68.6 19.55,68.5 24.46,68.5 24.56,68.4 24.66,68.4 24.75,68.51 24.72,69.16 24.81,69.26 C19.2
UNNAMED_1_74244_I71_A_3: length 8.6
  TOP w0.1: D23.4 19.35,66.45 19.45,66.35 19.45,66 19.55,65.9 22.3,65.9 23.4,64.8 24.71,64.8 24.81,64.9 24.81,65.5 24.91,65.6 C20.2

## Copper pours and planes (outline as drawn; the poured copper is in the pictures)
PGND on LAYER3, LAYER7, LAYER11, LAYER16: 0.2,0.2 281.74,0.2 281.74,187.76 0.2,187.76
P2_3V on LAYER4, LAYER8, LAYER12, LAYER15: 0.2,0.2 281.74,0.2 281.74,187.76 0.2,187.76

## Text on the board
User.Comments: Dynamic phase incl. pindelay | at transmitting end. | Static phase compensation | to manage pin delay at | reciever.
LAYER6: PHASEDELAY wrong direction. | Pintype TRI | PINTYPE set to OUT
